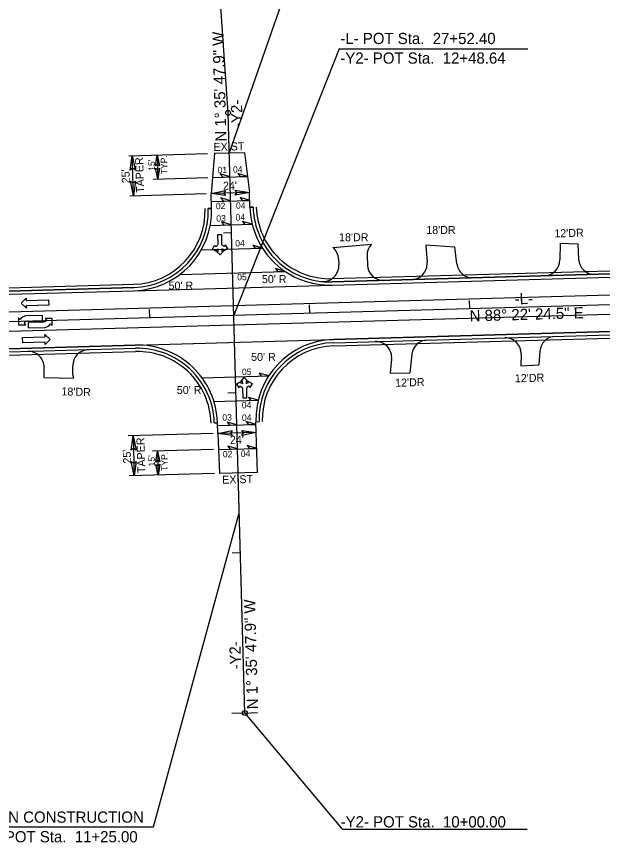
# Model space of a CAD drawing. Extents: x 1755545 to 1761252, y 736169 to 737766.
# Drawn here: x 1757301 to 1757667, y 736646 to 737162 of the extents above; entities that cross this region are included whole.
import ezdxf

# ---------------------------------------------------------------- set-up
doc = ezdxf.new("R2010")
doc.units = 0
for name, color, linetype in [('Exist Contamination Potential Cell', 7, 'Continuous'), ('Exist Cultural Church Label', 7, 'Continuous'), ('Old_Level_1', 7, 'Continuous'), ('Prop Dimension', 7, 'Continuous'), ('Prop Horizontal Alignment', 7, 'Continuous'), ('Prop Horizontal Alignment Direction Label', 7, 'Continuous'), ('Prop Horizontal Alignment Station Label', 7, 'Continuous'), ('Prop Horizontal Alignment Tick Large', 7, 'Continuous'), ('Prop Horizontal Alignment Tick Small', 7, 'Continuous'), ('Prop Lane Arrow CELL', 7, 'Continuous'), ('Prop Lane Lines', 7, 'Continuous'), ('Prop Paved Shoulder', 7, 'Continuous'), ('Prop Shade Light', 7, 'Continuous'), ('Prop Superelevation Label', 7, 'Continuous'), ('Prop Terminator CELL', 7, 'Continuous'), ('Scratch_Level_4', 7, 'Continuous'), ('Scratch_Level_6', 7, 'Continuous')]:
    doc.layers.add(name, color=color, linetype=linetype)

msp = doc.modelspace()

# ---------------------------------------------------------------- linework, layer by layer
at = {"layer": 'Exist Contamination Potential Cell'}
for p, q in [((1757424.33, 737076.59), (1757422.12, 737051.52)), ((1757424.33, 737076.59), (1757442.94, 737077.11)), ((1757442.94, 737077.11), (1757446.11, 737052.19)), ((1757422.38, 737042.13), (1757422.12, 737051.52)), ((1757446.37, 737042.87), (1757446.11, 737052.19)), ((1757498.66, 736960.29), (1760222.11, 737037.63)), ((1757497.77, 736994.28), (1758821.01, 737031.85)), ((1757285.16, 736988.24), (1757373.82, 736990.76)), ((1757286.12, 736954.26), (1757374.71, 736956.77)), ((1757426.3, 736901.58), (1757426.11, 736908.19)), ((1757450.29, 736902.25), (1757450.1, 736908.92)), ((1757426.3, 736901.58), (1757427.26, 736876.59)), ((1757451.21, 736877.26), (1757450.29, 736902.25)), ((1757451.21, 736877.26), (1757427.26, 736876.59))]:
    msp.add_line(p, q, dxfattribs=at)
for centre, start, end in [((1757372.4, 737040.74), 271.6265, 1.5966), ((1757496.35, 737044.26), 181.5966, 271.6265), ((1757376.13, 736906.79), 1.5966, 91.6265), ((1757500.08, 736910.31), 91.6265, 181.5966)]:
    msp.add_arc(centre, 50, start, end, dxfattribs=at)
at = {"layer": 'Exist Cultural Church Label'}
for points in [[(1757433.83, 737061.85), (1757427.78, 737063.68), (1757429.21, 737061.72)], [(1757444.84, 737062.16), (1757438.79, 737063.99), (1757440.22, 737062.03)], [(1757434.25, 737046.86), (1757428.2, 737048.69), (1757429.63, 737046.73)], [(1757446.25, 737047.19), (1757440.19, 737049.02), (1757441.62, 737047.06)], [(1757434.67, 737031.86), (1757428.62, 737033.69), (1757430.05, 737031.73)], [(1757447.82, 737032.23), (1757441.76, 737034.06), (1757443.19, 737032.1)], [(1757454.17, 737017.4), (1757448.12, 737019.23), (1757449.55, 737017.27)], [(1757468.41, 737002.79), (1757462.36, 737004.62), (1757463.79, 737002.66)], [(1757458.1, 736937.48), (1757452.05, 736939.31), (1757453.48, 736937.35)], [(1757451.54, 736922.29), (1757445.48, 736924.12), (1757446.91, 736922.16)], [(1757438.15, 736906.91), (1757432.1, 736908.74), (1757433.53, 736906.78)], [(1757450.15, 736907.24), (1757444.09, 736909.08), (1757445.52, 736907.12)], [(1757450.66, 736892.25), (1757444.6, 736894.08), (1757446.03, 736892.12)], [(1757438.57, 736891.92), (1757432.52, 736893.75), (1757433.95, 736891.79)]]:
    msp.add_lwpolyline(points, close=True, dxfattribs=at)
at = {"layer": 'Old_Level_1'}
for p, q in [((1757498.17, 737017.78), (1757522.41, 737019.82)), ((1757556.38, 737019.12), (1757557.09, 737008.34)), ((1757574.33, 737017.94), (1757556.38, 737019.12)), ((1757575.7, 737007.48), (1757574.33, 737017.94)), ((1757640.17, 737020.42), (1757640.07, 737009.95)), ((1757640.17, 737020.42), (1757651.28, 737019.94)), ((1757651.28, 737019.94), (1757651.76, 737010.44)), ((1757519.57, 737012.43), (1757519.8, 737006.79)), ((1757501.83, 737010.45), (1757501.98, 737006.93)), ((1757547.58, 736951.1), (1757546.23, 736939.38)), ((1757615.92, 736951.02), (1757615.69, 736943.86)), ((1757627.58, 736953.04), (1757626.87, 736944.37)), ((1757534.95, 736948.03), (1757534.06, 736939.28)), ((1757317.75, 736936.63), (1757317.77, 736942.83)), ((1757335.76, 736938.21), (1757335.65, 736943.74)), ((1757615.69, 736943.86), (1757626.87, 736944.37)), ((1757317.75, 736936.63), (1757336.16, 736936.1)), ((1757534.06, 736939.28), (1757546.23, 736939.38))]:
    msp.add_line(p, q, dxfattribs=at)
for centre, radius, start, end in [((1757491.84, 737010.04), 10, 2.3888, 50.7605), ((1757529.56, 737012.83), 10, 135.6525, 182.3156), ((1757547.11, 737007.69), 10, 271.6265, 3.7704), ((1757585.61, 737008.78), 10, 187.4572, 271.6265), ((1757630.07, 737010.04), 10, 271.6265, 359.4649), ((1757661.74, 737010.94), 10, 182.8977, 271.6265), ((1757491.99, 737006.51), 10, 263.4115, 2.3888), ((1757529.79, 737007.19), 10, 182.3156, 271.6265), ((1757605.92, 736951.33), 10, 358.2039, 91.6265), ((1757637.54, 736952.23), 10, 91.6265, 175.3403), ((1757525, 736949.03), 10, 354.2066, 91.6265), ((1757557.51, 736949.96), 10, 91.6265, 173.4454), ((1757307.77, 736942.87), 10, 359.8121, 91.6265), ((1757345.65, 736943.94), 10, 91.6265, 181.133), ((1757341.66, 736938.24), 5.89, 180.2747, 201.2516)]:
    msp.add_arc(centre, radius, start, end, dxfattribs=at)
at = {"layer": 'Prop Dimension'}
for p, q in [((1757370.73, 737075.1), (1757419.92, 737076.47)), ((1757373.54, 737050.17), (1757372.84, 737075.16)), ((1757371.42, 737050.11), (1757419.12, 737051.44)), ((1757446.11, 737052.19), (1757422.12, 737051.52)), ((1757423.3, 736901.49), (1757370.32, 736900.02)), ((1757373.32, 736900.1), (1757374.01, 736875.11)), ((1757450.29, 736902.25), (1757426.3, 736901.58)), ((1757424.26, 736876.51), (1757371.01, 736875.03))]:
    msp.add_line(p, q, dxfattribs=at)
at = {"layer": 'Prop Horizontal Alignment'}
for p, q in [((1757443.17, 736726.98), (1757432.72, 737101.83)), ((1757285.64, 736971.25), (1760282.69, 737056.35))]:
    msp.add_line(p, q, dxfattribs=at)
at = {"layer": 'Prop Horizontal Alignment Station Label'}
for p, q in [((1757432.72, 737101.83), (1757424.01, 737228.79)), ((1757486.62, 737228.79), (1757433.41, 737076.84)), ((1757502.2, 737141.84), (1757436.24, 736975.53)), ((1757502.2, 737141.84), (1757619.97, 737141.84)), ((1757386.1, 736655.79), (1757439.68, 736851.93)), ((1757443.17, 736726.98), (1757503.92, 736654.45)), ((1757272.78, 736655.79), (1757386.1, 736655.79)), ((1757503.92, 736654.45), (1757619.73, 736654.45))]:
    msp.add_line(p, q, dxfattribs=at)
for centre in [(1757432.72, 737101.83), (1757443.17, 736726.98)]:
    msp.add_circle(centre, 1.5, dxfattribs=at)
at = {"layer": 'Prop Horizontal Alignment Tick Large'}
for q in [(1757435.17, 736726.76), (1757451.16, 736727.2)]:
    msp.add_line((1757443.17, 736726.98), q, dxfattribs=at)
at = {"layer": 'Prop Horizontal Alignment Tick Small'}
for p, q in [((1757434.81, 737026.86), (1757429.81, 737026.72)), ((1757483.81, 736976.88), (1757483.67, 736981.88)), ((1757583.78, 736979.72), (1757583.64, 736984.71)), ((1757383.86, 736974.04), (1757383.72, 736979.04)), ((1757437.59, 736926.9), (1757432.6, 736926.76)), ((1757440.38, 736826.94), (1757435.38, 736826.8))]:
    msp.add_line(p, q, dxfattribs=at)
at = {"layer": 'Prop Lane Arrow CELL'}
for p, q in [((1757426.3, 737025.9), (1757428.51, 737025.96)), ((1757426.47, 737019.9), (1757426.3, 737025.9)), ((1757428.51, 737025.96), (1757428.67, 737019.92)), ((1757422.9, 737016.7), (1757424.29, 737019.23)), ((1757424.29, 737019.23), (1757424.6, 737018.31)), ((1757430.63, 737018.48), (1757430.89, 737019.41)), ((1757430.89, 737019.41), (1757432.38, 737016.97)), ((1757425.5, 737015.32), (1757422.9, 737016.7)), ((1757425.19, 737016.23), (1757425.5, 737015.32)), ((1757425.68, 737015.11), (1757426.6, 737015.14)), ((1757427.8, 737013.07), (1757425.68, 737015.11)), ((1757426.6, 737015.14), (1757426.55, 737016.98)), ((1757429.73, 737015.22), (1757427.8, 737013.07)), ((1757428.76, 737017.01), (1757428.81, 737015.2)), ((1757428.81, 737015.2), (1757429.73, 737015.22)), ((1757432.38, 737016.97), (1757429.9, 737015.44)), ((1757429.9, 737015.44), (1757430.16, 737016.37)), ((1757303.43, 736982.87), (1757306.48, 736986.16)), ((1757306.66, 736979.86), (1757303.43, 736982.87)), ((1757306.48, 736986.16), (1757306.53, 736984.66)), ((1757306.53, 736984.66), (1757320.52, 736985.06)), ((1757320.61, 736981.76), (1757306.62, 736981.36)), ((1757320.52, 736985.06), (1757320.61, 736981.76)), ((1757306.62, 736981.36), (1757306.66, 736979.86)), ((1757302.82, 736972.83), (1757301.69, 736973.85)), ((1757301.69, 736973.85), (1757301.82, 736969.4)), ((1757316.76, 736975.33), (1757306.21, 736975.03)), ((1757307.71, 736971.77), (1757316.85, 736972.03)), ((1757316.85, 736972.03), (1757316.76, 736975.33)), ((1757322.81, 736973.45), (1757318.31, 736973.37)), ((1757318.31, 736973.37), (1757319.39, 736972.35)), ((1757322.89, 736969.05), (1757322.81, 736973.45)), ((1757301.82, 736969.4), (1757306.32, 736969.53)), ((1757306.32, 736969.53), (1757305.24, 736970.55)), ((1757316.93, 736971.13), (1757307.78, 736970.87)), ((1757307.78, 736970.87), (1757307.87, 736967.57)), ((1757307.87, 736967.57), (1757318.42, 736967.87)), ((1757321.81, 736970.07), (1757322.89, 736969.05)), ((1757304.31, 736961.45), (1757318.31, 736961.85)), ((1757304.41, 736958.15), (1757304.31, 736961.45)), ((1757318.31, 736961.85), (1757318.26, 736963.35)), ((1757318.26, 736963.35), (1757321.5, 736960.34)), ((1757318.4, 736958.55), (1757304.41, 736958.15)), ((1757318.44, 736957.05), (1757318.4, 736958.55)), ((1757321.5, 736960.34), (1757318.44, 736957.05)), ((1757440.89, 736934.31), (1757442.82, 736936.47)), ((1757442.82, 736936.47), (1757444.94, 736934.43)), ((1757438.23, 736932.57), (1757440.72, 736934.1)), ((1757439.72, 736930.12), (1757438.23, 736932.57)), ((1757439.98, 736931.05), (1757439.72, 736930.12)), ((1757440.72, 736934.1), (1757440.46, 736933.16)), ((1757441.81, 736934.34), (1757440.89, 736934.31)), ((1757441.86, 736932.53), (1757441.81, 736934.34)), ((1757444.94, 736934.43), (1757444.01, 736934.4)), ((1757444.01, 736934.4), (1757444.07, 736932.55)), ((1757445.43, 736933.3), (1757445.12, 736934.22)), ((1757445.12, 736934.22), (1757447.72, 736932.83)), ((1757446.33, 736930.31), (1757446.02, 736931.22)), ((1757447.72, 736932.83), (1757446.33, 736930.31)), ((1757442.11, 736923.58), (1757441.94, 736929.62)), ((1757444.15, 736929.64), (1757444.31, 736923.64)), ((1757444.31, 736923.64), (1757442.11, 736923.58))]:
    msp.add_line(p, q, dxfattribs=at)
for centre, radius, start, end in [((1757423.92, 737021.15), 2.91, 283.2297, 314.1599), ((1757424.87, 737020.32), 1.66, 310.6698, 345.4358), ((1757430.24, 737020.47), 1.66, 199.5256, 232.5235), ((1757431.14, 737021.35), 2.91, 229.0334, 260.2461), ((1757424.54, 737019.07), 2.91, 282.8605, 313.7502), ((1757430.63, 737019.24), 2.91, 229.8399, 260.6163), ((1757307.14, 736969.85), 5.25, 100.3026, 145.6143), ((1757307.78, 736968.48), 3.28, 91.6265, 141.2847), ((1757316.84, 736974.39), 3.28, 271.6265, 321.2847), ((1757317.48, 736973.02), 5.25, 280.3026, 325.6143), ((1757439.48, 736928.18), 2.91, 49.0334, 80.2461), ((1757439.98, 736930.29), 2.91, 49.8399, 80.6163), ((1757440.38, 736929.07), 1.66, 19.5256, 52.5235), ((1757446.08, 736930.46), 2.91, 102.8605, 133.7502), ((1757445.75, 736929.21), 1.66, 130.6698, 165.4358), ((1757446.7, 736928.38), 2.91, 103.2297, 134.1599)]:
    msp.add_arc(centre, radius, start, end, dxfattribs=at)
at = {"layer": 'Prop Lane Lines'}
for p, q in [((1757285.47, 736977.25), (1760207.53, 737060.22)), ((1757285.81, 736965.25), (1760207.87, 737048.23)), ((1757373.82, 736990.76), (1757497.77, 736994.28)), ((1757374.71, 736956.77), (1757498.66, 736960.29))]:
    msp.add_line(p, q, dxfattribs=at)
at = {"layer": 'Prop Paved Shoulder'}
for p, q in [((1757420.38, 737042.08), (1757422.38, 737042.13)), ((1757446.37, 737042.87), (1757448.37, 737042.92)), ((1757497.71, 736996.28), (1758820.95, 737033.85)), ((1757285.1, 736990.24), (1757373.76, 736992.76)), ((1757498.72, 736958.29), (1758854.08, 736996.78)), ((1757286.18, 736952.26), (1757374.77, 736954.77)), ((1757424.11, 736908.13), (1757426.11, 736908.19)), ((1757450.1, 736908.92), (1757452.1, 736908.97))]:
    msp.add_line(p, q, dxfattribs=at)
for centre, start, end in [((1757372.4, 737040.74), 271.6265, 1.5966), ((1757496.35, 737044.26), 181.5966, 271.6265), ((1757500.08, 736910.31), 91.6265, 181.5966), ((1757376.13, 736906.79), 1.5966, 91.6265)]:
    msp.add_arc(centre, 48, start, end, dxfattribs=at)
at = {"layer": 'Prop Shade Light'}
for p, q in [((1757422.38, 737042.13), (1757420.38, 737042.08)), ((1757448.37, 737042.92), (1757446.37, 737042.87)), ((1758820.95, 737033.85), (1757497.71, 736996.28)), ((1760222.11, 737037.63), (1757498.66, 736960.29)), ((1757497.77, 736994.28), (1758821.01, 737031.85)), ((1757498.72, 736958.29), (1758862.05, 736997.01)), ((1757373.76, 736992.76), (1757285.1, 736990.24)), ((1757285.16, 736988.24), (1757373.82, 736990.76)), ((1757374.71, 736956.77), (1757286.12, 736954.26)), ((1757286.18, 736952.26), (1757374.77, 736954.77)), ((1757424.11, 736908.13), (1757426.11, 736908.19)), ((1757450.1, 736908.92), (1757452.1, 736908.97))]:
    msp.add_line(p, q, dxfattribs=at)
for centre, radius, start, end in [((1757372.4, 737040.74), 48, 271.6265, 1.5966), ((1757372.4, 737040.74), 50, 271.6265, 1.5966), ((1757496.35, 737044.26), 50, 181.5966, 271.6265), ((1757496.35, 737044.26), 48, 181.5966, 271.6265), ((1757376.13, 736906.79), 50, 1.5966, 91.6265), ((1757500.08, 736910.31), 50, 91.6265, 181.5966), ((1757500.08, 736910.31), 48, 91.6265, 181.5966), ((1757376.13, 736906.79), 48, 1.5966, 91.6265)]:
    msp.add_arc(centre, radius, start, end, dxfattribs=at)
at = {"layer": 'Prop Superelevation Label'}
for p, q in [((1757388.43, 737075.59), (1757388.85, 737060.6)), ((1757385.85, 737060.51), (1757420, 737061.46)), ((1757423, 737061.55), (1757444.84, 737062.16)), ((1757422.26, 737046.52), (1757446.25, 737047.19)), ((1757421.54, 737031.5), (1757447.82, 737032.23)), ((1757416.04, 737016.34), (1757454.17, 737017.4)), ((1757402.69, 737000.96), (1757468.41, 737002.79)), ((1757416.48, 736936.32), (1757458.1, 736937.48)), ((1757423.91, 736921.52), (1757451.54, 736922.29)), ((1757426.16, 736906.58), (1757450.15, 736907.24)), ((1757423.68, 736891.5), (1757385.59, 736890.44)), ((1757388.59, 736890.52), (1757389.01, 736875.53)), ((1757426.68, 736891.58), (1757450.66, 736892.25))]:
    msp.add_line(p, q, dxfattribs=at)
at = {"layer": 'Prop Terminator CELL'}
for points in [[(1757371.54, 737066.12), (1757372.84, 737075.16), (1757374.69, 737066.15), (1757373.06, 737067.26)], [(1757387.46, 737068.81), (1757388.43, 737075.59), (1757389.82, 737068.84), (1757388.6, 737069.67)], [(1757389.82, 737067.38), (1757388.85, 737060.6), (1757387.46, 737067.35), (1757388.69, 737066.52)], [(1757374.84, 737059.2), (1757373.54, 737050.17), (1757371.69, 737059.17), (1757373.32, 737058.06)], [(1757431.16, 737050.22), (1757422.12, 737051.52), (1757431.12, 737053.37), (1757430.01, 737051.74)], [(1757437.07, 737053.49), (1757446.11, 737052.19), (1757437.1, 737050.34), (1757438.21, 737051.97)], [(1757372.06, 736891.05), (1757373.32, 736900.1), (1757375.21, 736891.11), (1757373.58, 736892.21)], [(1757435.34, 736900.28), (1757426.3, 736901.58), (1757435.3, 736903.43), (1757434.19, 736901.8)], [(1757441.25, 736903.54), (1757450.29, 736902.25), (1757441.28, 736900.39), (1757442.39, 736902.03)], [(1757387.61, 736883.74), (1757388.59, 736890.52), (1757389.98, 736883.77), (1757388.75, 736884.6)], [(1757375.27, 736884.16), (1757374.01, 736875.11), (1757372.12, 736884.1), (1757373.75, 736883.01)], [(1757389.98, 736882.31), (1757389.01, 736875.53), (1757387.62, 736882.28), (1757388.84, 736881.45)]]:
    msp.add_lwpolyline(points, close=True, dxfattribs=at)
at = {"layer": 'Scratch_Level_6'}
for p, q in [((1757497.65, 736998.28), (1758820.89, 737035.85)), ((1757285.04, 736992.24), (1757373.7, 736994.76)), ((1757498.78, 736956.29), (1758854.11, 736994.78)), ((1757286.23, 736950.26), (1757374.83, 736952.77))]:
    msp.add_line(p, q, dxfattribs=at)
for centre, start, end in [((1757372.4, 737040.74), 271.6265, 1.5966), ((1757496.35, 737044.26), 181.5966, 271.6265), ((1757500.08, 736910.31), 91.6265, 181.5966), ((1757376.13, 736906.79), 1.5966, 91.6265)]:
    msp.add_arc(centre, 46, start, end, dxfattribs=at)

# ---------------------------------------------------------------- texts
at = {"layer": 'Prop Dimension'}
for s, rotation, p in [('EXIST', 1.5966, (1757423.66, 737078)), ('TAPER', 91.889, (1757380.31, 737051.9)), ("25'", 91.889, (1757371.36, 737057.91)), ("24'", 1.5966, (1757429.59, 737053.77)), ("24'", 1.5966, (1757433.94, 736895.07)), ('TAPER', 91.889, (1757381.13, 736876.87)), ("25'", 91.889, (1757372.18, 736882.88)), ('EXIST', 1.5966, (1757429.11, 736870.16))]:
    msp.add_text(s, height=5, rotation=rotation, dxfattribs=at).set_placement(p)
for p in [(1757453.83, 736995.49), (1757395.52, 736991.44), (1757447.11, 736946.88), (1757400.67, 736926.24)]:
    msp.add_text("50' R", height=5, dxfattribs=at).set_placement(p)
at = {"layer": 'Prop Horizontal Alignment Direction Label'}
for s, rotation, p in [('N 1%%d 35\' 47.9" W', 91.5966, (1757431.8, 737084)), ('-Y2-', 91.5966, (1757441.86, 737092.49)), ('-L-', 1.6265, (1757611.86, 736982.2)), ('N 88%%d 22\' 24.5" E', 1.6265, (1757583.77, 736971.52)), ('N 1%%d 35\' 47.9" W', 91.5966, (1757451.52, 736729.39)), ('-Y2-', 91.5966, (1757440.93, 736754.24))]:
    msp.add_text(s, height=7, rotation=rotation, dxfattribs=at).set_placement(p)
at = {"layer": 'Prop Horizontal Alignment Station Label'}
for s, p in [('-L- POT Sta.  27+52.40', (1757502.88, 737144.81)), ('-Y2- POT Sta.  12+48.64', (1757502.88, 737132.56)), ('BEGIN CONSTRUCTION', (1757272.93, 736658.46)), ('-Y2- POT Sta.  11+25.00', (1757272.93, 736646.21))]:
    msp.add_text(s, height=7, rotation=360, dxfattribs=at).set_placement(p)
msp.add_text('-Y2- POT Sta.  10+00.00', height=7, dxfattribs=at).set_placement((1757503.04, 736655.51))
at = {"layer": 'Prop Superelevation Label'}
for s, rotation, p in [('TYP.', 90.6974, (1757394.75, 737063.53)), ("15'", 90.6974, (1757387, 737065.68)), ('01', 1.5966, (1757426.22, 737064.1)), ('04', 1.5966, (1757435.85, 737064.41)), ('02', 1.5966, (1757425.15, 737041.63)), ('04', 1.5966, (1757437.71, 737041.85)), ('04', 1.5966, (1757437.47, 737034.49)), ('03', 1.5966, (1757425.43, 737033.9)), ('04', 1.5966, (1757437.24, 737018.36)), ('05', 1.5966, (1757438.47, 736997.21)), ('05', 1.5966, (1757441.44, 736938.03)), ('04', 1.5966, (1757441.36, 736917.22)), ('03', 1.5966, (1757429.2, 736909.51)), ('04', 1.5966, (1757441.44, 736909.37)), ('TYP.', 90.6974, (1757395.06, 736878.25)), ('02', 1.5966, (1757429.52, 736886.59)), ('04', 1.5966, (1757440.75, 736886.91)), ("15'", 90.6974, (1757387.02, 736881.02))]:
    msp.add_text(s, height=4, rotation=rotation, dxfattribs=at).set_placement(p)
at = {"layer": 'Scratch_Level_4'}
for s, rotation, p in [("18'DR", 360, (1757556.56, 737026.18)), ("12'DR", 1.6265, (1757636.69, 737024.01)), ("18'DR", 360, (1757502.08, 737021.66)), ("12'DR", 1.6265, (1757537.18, 736930.73)), ("12'DR", 1.6265, (1757612.03, 736933.51)), ("18'DR", 358.3585, (1757328.53, 736925.4))]:
    msp.add_text(s, height=5, rotation=rotation, dxfattribs=at).set_placement(p)

doc.saveas('drawing.dxf')
